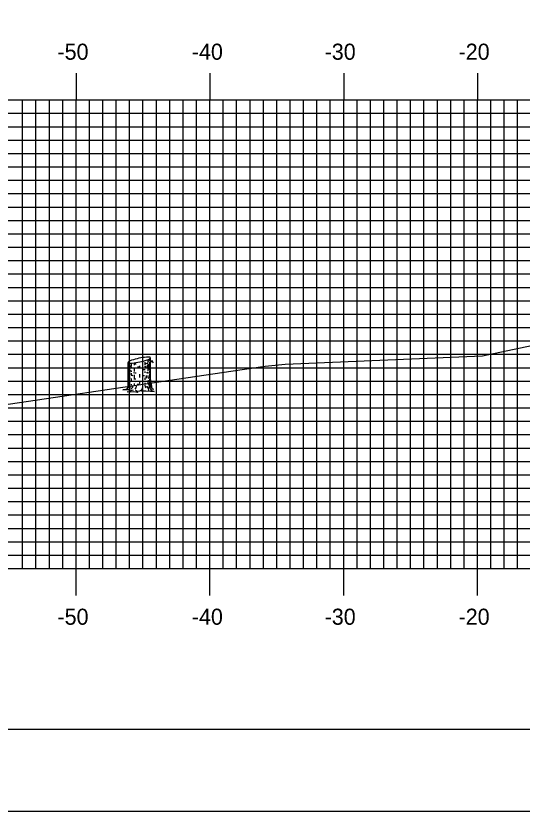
# Model space of a CAD drawing. Extents: x 852542 to 852886, y 364366 to 364586.
# Drawn here: x 852653.7 to 852691.5, y 364365.7 to 364425.1 of the extents above; entities that cross this region are included whole.
import ezdxf

# ---------------------------------------------------------------- set-up
doc = ezdxf.new("R2010")
doc.units = 0
for name, color, linetype in [('BORDER', 7, 'Continuous'), ('H_V ANNOTATION', 7, 'Continuous'), ('M_Trees_Conifer_Pay', 7, 'Continuous'), ('MAJOR', 7, 'Continuous'), ('MINOR', 7, 'Continuous'), ('PLOT BOUNDARY', 7, 'Continuous'), ('S_Roadway_Centerline', 7, 'Continuous')]:
    doc.layers.add(name, color=color, linetype=linetype)

msp = doc.modelspace()

# ---------------------------------------------------------------- linework, layer by layer
at = {"layer": 'BORDER'}
msp.add_lwpolyline([(852558.578, 364371.787), (852878.578, 364371.787), (852878.578, 364581.787), (852558.578, 364581.787)], close=True, dxfattribs=at)
at = {"layer": 'M_Trees_Conifer_Pay'}
for p, q in [((852663.548, 364399.388), (852663.548, 364399.165)), ((852663.666, 364399.449), (852663.666, 364399.287)), ((852663.737, 364397.875), (852663.737, 364399.522)), ((852662.073, 364397.465), (852662.073, 364399.186)), ((852662.12, 364399.149), (852662.12, 364398.678)), ((852662.179, 364399.138), (852662.179, 364399.04)), ((852662.179, 364398.966), (852662.179, 364398.762)), ((852662.304, 364399.13), (852662.304, 364398.898)), ((852662.304, 364398.857), (852662.304, 364398.783)), ((852662.524, 364399.15), (852662.524, 364398.982)), ((852662.524, 364398.745), (852662.524, 364398.509)), ((852662.929, 364398.919), (852662.929, 364398.824)), ((852663.32, 364399.192), (852663.32, 364398.993)), ((852663.32, 364398.935), (852663.32, 364398.846)), ((852663.548, 364399.077), (852663.548, 364399.03)), ((852663.605, 364398.894), (852663.554, 364398.834)), ((852663.666, 364399.219), (852663.666, 364399.091)), ((852663.666, 364398.904), (852663.666, 364398.568)), ((852662.12, 364398.614), (852662.12, 364398.305)), ((852662.12, 364398.258), (852662.12, 364397.766)), ((852662.179, 364398.704), (852662.179, 364398.505)), ((852662.179, 364398.457), (852662.179, 364398.121)), ((852662.304, 364398.379), (852662.304, 364398.241)), ((852662.524, 364398.264), (852662.524, 364398.112)), ((852662.929, 364398.305), (852662.929, 364398.231)), ((852662.929, 364398.206), (852662.929, 364398.058)), ((852663.32, 364398.499), (852663.32, 364398.394)), ((852663.548, 364398.694), (852663.548, 364398.562)), ((852663.548, 364398.451), (852663.548, 364398.342)), ((852663.548, 364398.206), (852663.548, 364398.064)), ((852663.666, 364398.532), (852663.666, 364398.369)), ((852663.666, 364398.322), (852663.666, 364398.105)), ((852662.12, 364397.712), (852662.12, 364397.465)), ((852662.179, 364398.068), (852662.179, 364397.932)), ((852662.179, 364397.833), (852662.179, 364397.455)), ((852662.304, 364397.969), (852662.304, 364397.827)), ((852662.304, 364397.566), (852662.304, 364397.471)), ((852662.524, 364398.068), (852662.524, 364397.895)), ((852662.524, 364397.617), (852662.524, 364397.465)), ((852662.929, 364397.766), (852662.929, 364397.613)), ((852663.32, 364398.027), (852663.32, 364397.881)), ((852663.32, 364397.648), (852663.32, 364397.56)), ((852663.548, 364397.837), (852663.548, 364397.665)), ((852663.666, 364398.074), (852663.666, 364398)), ((852663.666, 364397.959), (852663.666, 364397.786)), ((852662.304, 364397.072), (852662.467, 364397.135)), ((852662.741, 364397.007), (852662.615, 364397.072))]:
    msp.add_line(p, q, dxfattribs=at)
for points in [[(852663.521, 364398.982), (852663.49, 364398.898), (852663.486, 364398.83), (852663.517, 364398.766)], [(852663.554, 364399.02), (852663.591, 364398.946), (852663.638, 364399.003), (852663.696, 364399.071), (852663.788, 364399.264), (852663.853, 364399.312), (852663.884, 364399.318)], [(852663.569, 364398.766), (852663.605, 364398.894), (852663.669, 364399.009), (852663.7, 364399.077), (852663.769, 364399.223)], [(852663.783, 364399.253), (852663.859, 364399.261), (852663.931, 364399.161)], [(852662.252, 364398.492), (852662.246, 364398.587), (852662.29, 364398.564), (852662.29, 364398.47)], [(852663.391, 364398.093), (852663.404, 364398.016), (852663.451, 364398.027), (852663.439, 364398.194)], [(852663.737, 364397.875), (852663.788, 364397.613), (852663.805, 364397.339), (852663.863, 364397.214), (852663.998, 364397.183), (852663.768, 364397.146), (852663.768, 364397.146), (852663.774, 364397.098), (852664.021, 364397.004), (852663.747, 364397.02), (852663.391, 364397.041), (852663.07, 364397.03), (852663.076, 364397.113), (852662.928, 364397.03), (852662.741, 364397.007), (852662.765, 364396.94), (852662.498, 364396.983), (852662.277, 364396.956), (852661.985, 364396.973), (852662.273, 364397.03), (852662.304, 364397.072), (852662.141, 364397.129), (852661.905, 364397.14), (852661.664, 364397.14), (852662.006, 364397.198), (852662.047, 364397.278), (852662.073, 364397.465)], [(852663.564, 364397.587), (852663.638, 364397.482), (852663.643, 364397.308), (852663.768, 364397.146)], [(852663.663, 364397.732), (852663.669, 364397.587), (852663.716, 364397.518), (852663.727, 364397.319)], [(852662.121, 364397.417), (852662.1, 364397.339), (852662.08, 364397.245)], [(852662.199, 364397.397), (852662.205, 364397.282), (852662.152, 364397.193), (852662.141, 364397.129)], [(852662.362, 364397.424), (852662.362, 364397.292), (852662.273, 364397.193)], [(852662.588, 364397.183), (852662.656, 364397.278), (852662.683, 364397.417)], [(852663.076, 364397.113), (852663.151, 364397.255), (852663.16, 364397.356)], [(852663.327, 364397.482), (852663.338, 364397.356), (852663.412, 364397.312)], [(852663.605, 364397.093), (852663.591, 364397.23), (852663.517, 364397.36)]]:
    msp.add_lwpolyline(points, dxfattribs=at)
for centre, radius, start, end in [((852662.572, 364398.58), 0.802, 108.05939, 124.2194), ((852663.929, 364394.419), 5.179, 101.7194, 108.05939), ((852663.929, 364394.419), 5.179, 95.37941, 101.7194), ((852661.882, 364404.289), 5.179, 281.7194, 288.05939), ((852663.519, 364398.777), 0.802, 79.2194, 95.37941), ((852663.238, 364400.128), 0.802, 288.05939, 304.2194), ((852663.622, 364399.318), 0.251, 71.05013, 79.2194), ((852663.548, 364399.672), 0.251, 304.2194, 312.38868), ((852663.605, 364399.49), 0.172, 300, 311.25059), ((852663.677, 364399.478), 0.0817, 56.7194, 71.05013), ((852663.662, 364399.547), 0.0817, 312.38868, 326.7194), ((852663.678, 364399.408), 0.0624, 311.25059, 330), ((852663.692, 364399.502), 0.0527, 46.92298, 56.7194), ((852663.707, 364399.518), 0.0314, 34.2194, 46.92298), ((852663.686, 364399.531), 0.0527, 326.7194, 336.51582), ((852663.694, 364399.398), 0.0441, 330, 343.94846), ((852663.711, 364399.52), 0.0264, 23.40735, 34.2194), ((852663.715, 364399.522), 0.0226, 11.7194, 23.40735), ((852663.706, 364399.523), 0.0314, 336.51582, 349.2194), ((852663.704, 364399.395), 0.0334, 343.94846, 354.21506), ((852663.715, 364399.522), 0.0226, 0.03145, 11.7194), ((852663.711, 364399.522), 0.0264, 349.2194, 0.03145), ((852662.105, 364399.008), 0.0334, 163.94846, 180), ((852662.105, 364399.008), 0.0334, 180, 196.05154), ((852662.1, 364399.186), 0.0264, 169.2194, 180.03145), ((852662.096, 364399.186), 0.0226, 180.03145, 191.7194), ((852662.116, 364399.011), 0.0441, 196.05154, 210), ((852662.105, 364399.185), 0.0314, 156.51582, 169.2194), ((852662.096, 364399.186), 0.0226, 191.7194, 203.40735), ((852662.099, 364399.188), 0.0264, 203.40735, 214.2194), ((852662.124, 364399.177), 0.0527, 146.7194, 156.51582), ((852662.131, 364399.02), 0.0624, 210, 228.74941), ((852662.104, 364399.19), 0.0314, 214.2194, 226.92298), ((852662.148, 364399.161), 0.0817, 132.38868, 146.7194), ((852662.118, 364399.206), 0.0527, 226.92298, 236.7194), ((852662.134, 364399.23), 0.0817, 236.7194, 251.05013), ((852662.204, 364399.103), 0.172, 228.74941, 240), ((852662.262, 364399.036), 0.251, 124.2194, 132.38868), ((852662.189, 364399.39), 0.251, 251.05013, 259.2194), ((852662.403, 364399.448), 0.571, 240, 240.33672), ((852662.404, 364399.237), 0.571, 240, 247.05866), ((852662.292, 364399.931), 0.802, 259.2194, 275.37941), ((852662.403, 364399.448), 0.571, 246.85973, 257.98457), ((852661.882, 364404.289), 5.179, 275.37941, 281.7194), ((852662.905, 364403.198), 4.124, 264.6955, 266.73309), ((852662.904, 364402.965), 4.124, 268.07512, 270), ((852662.904, 364402.965), 4.124, 270, 270.35814), ((852662.904, 364402.965), 4.124, 275.78493, 277.05584), ((852662.905, 364403.198), 4.124, 276.23804, 278.1032), ((852663.406, 364399.681), 0.571, 278.1032, 284.36665), ((852663.406, 364399.835), 0.571, 284.43166, 292.41325), ((852663.406, 364399.237), 0.571, 284.44928, 297.04285), ((852663.406, 364399.681), 0.571, 297.0237, 300), ((852663.605, 364399.336), 0.172, 300, 311.25059), ((852663.678, 364399.253), 0.0624, 311.25059, 330), ((852663.694, 364399.244), 0.0441, 330, 343.94846), ((852663.704, 364399.241), 0.0334, 343.94846, 354.21506), ((852663.704, 364398.797), 0.0334, 343.94846, 354.21506), ((852662.105, 364398.561), 0.0334, 163.94846, 180), ((852662.105, 364398.561), 0.0334, 180, 196.05154), ((852662.105, 364398.351), 0.0334, 163.94846, 180), ((852662.105, 364398.351), 0.0334, 180, 196.05154), ((852662.116, 364398.564), 0.0441, 196.05154, 210), ((852662.116, 364398.354), 0.0441, 196.05154, 210), ((852662.131, 364398.573), 0.0624, 210, 228.74941), ((852662.131, 364398.363), 0.0624, 210, 228.74941), ((852662.204, 364398.656), 0.172, 228.74941, 240), ((852662.204, 364398.446), 0.172, 228.74941, 240), ((852662.403, 364399.001), 0.571, 240, 240.33672), ((852662.403, 364398.791), 0.571, 240, 246.85973), ((852662.403, 364398.791), 0.571, 259.27072, 261.8968), ((852662.904, 364402.309), 4.124, 261.8968, 263.14738), ((852662.904, 364402.519), 4.124, 264.08098, 266.66759), ((852662.904, 364402.309), 4.124, 270, 270.35814), ((852662.904, 364402.309), 4.124, 273.14934, 275.45691), ((852662.905, 364402.754), 4.124, 273.70524, 275.95043), ((852662.904, 364402.519), 4.124, 277.61247, 278.1032), ((852663.405, 364399.001), 0.571, 278.1032, 286.92962), ((852663.405, 364399.001), 0.571, 297.18959, 300), ((852663.405, 364398.791), 0.571, 297.18959, 300), ((852663.604, 364398.656), 0.172, 300, 311.25059), ((852663.604, 364398.446), 0.172, 300, 311.25059), ((852663.676, 364398.573), 0.0624, 311.25059, 330), ((852663.676, 364398.363), 0.0624, 311.25059, 330), ((852663.692, 364398.564), 0.0441, 330, 343.94846), ((852663.692, 364398.354), 0.0441, 330, 343.94846), ((852663.703, 364398.561), 0.0334, 343.94846, 354.21506), ((852663.703, 364398.351), 0.0334, 343.94846, 354.21506), ((852662.105, 364398.115), 0.0334, 163.94846, 180), ((852662.105, 364398.115), 0.0334, 180, 196.05154), ((852662.105, 364397.917), 0.0334, 163.94846, 180), ((852662.105, 364397.721), 0.0334, 163.94846, 180), ((852662.105, 364397.721), 0.0334, 180, 196.05154), ((852662.116, 364398.117), 0.0441, 196.05154, 210), ((852662.116, 364397.724), 0.0441, 196.05154, 210), ((852662.131, 364398.127), 0.0624, 210, 228.74941), ((852662.131, 364397.733), 0.0624, 210, 228.74941), ((852662.204, 364398.209), 0.172, 228.74941, 240), ((852662.204, 364397.816), 0.172, 228.74941, 240), ((852662.403, 364398.554), 0.571, 240, 246.85973), ((852662.392, 364398.363), 0.571, 241.23686, 248.02677), ((852662.403, 364398.161), 0.571, 240, 246.85973), ((852662.904, 364401.874), 4.124, 263.49906, 265.83975), ((852662.904, 364402.072), 4.124, 264.71603, 266.31934), ((852662.904, 364401.679), 4.124, 267.81166, 270), ((852662.904, 364401.679), 4.124, 270, 270.13279), ((852662.904, 364401.679), 4.124, 275.78493, 276.78961), ((852663.405, 364398.554), 0.571, 285.39827, 297.18959), ((852663.405, 364398.161), 0.571, 288.50673, 297.27208), ((852663.405, 364398.357), 0.571, 289.29072, 300), ((852663.604, 364398.012), 0.172, 300, 311.25059), ((852663.676, 364397.929), 0.0624, 311.25059, 330), ((852663.692, 364397.92), 0.0441, 330, 343.94846), ((852663.703, 364397.917), 0.0334, 343.94846, 354.21506), ((852662.105, 364397.501), 0.0334, 163.94846, 180), ((852662.105, 364397.501), 0.0334, 180, 196.05154), ((852662.116, 364397.504), 0.0441, 196.05154, 210), ((852662.131, 364397.513), 0.0624, 210, 228.74941), ((852662.204, 364397.596), 0.172, 228.74941, 240), ((852662.403, 364397.941), 0.571, 240, 244.53138), ((852662.904, 364401.458), 4.124, 262.44379, 263.51202), ((852662.904, 364401.458), 4.124, 277.36842, 278.1032), ((852663.405, 364397.941), 0.571, 278.1032, 281.63703), ((852663.604, 364397.596), 0.172, 300, 311.25059), ((852663.676, 364397.513), 0.0624, 311.25059, 330), ((852663.692, 364397.504), 0.0441, 330, 343.94846), ((852663.703, 364397.501), 0.0334, 343.94846, 354.21506)]:
    msp.add_arc(centre, radius, start, end, dxfattribs=at)
at = {"layer": 'MAJOR'}
for p, q in [((852658.178, 364420.791), (852658.178, 364418.787)), ((852668.178, 364420.791), (852668.178, 364418.787)), ((852678.178, 364420.791), (852678.178, 364418.787)), ((852688.178, 364420.791), (852688.178, 364418.787)), ((852568.178, 364418.787), (852848.178, 364418.787)), ((852568.178, 364418.787), (852848.178, 364418.787)), ((852658.178, 364383.787), (852658.178, 364418.787)), ((852668.178, 364383.787), (852668.178, 364418.787)), ((852678.178, 364383.787), (852678.178, 364418.787)), ((852688.178, 364383.787), (852688.178, 364418.787)), ((852568.178, 364413.787), (852848.178, 364413.787)), ((852568.178, 364408.787), (852848.178, 364408.787)), ((852568.178, 364403.787), (852848.178, 364403.787)), ((852568.178, 364398.787), (852848.178, 364398.787)), ((852568.178, 364393.787), (852848.178, 364393.787)), ((852568.178, 364388.787), (852848.178, 364388.787)), ((852568.178, 364383.787), (852848.178, 364383.787)), ((852568.178, 364383.787), (852848.178, 364383.787)), ((852658.178, 364381.783), (852658.178, 364383.787)), ((852668.178, 364381.783), (852668.178, 364383.787)), ((852678.178, 364381.783), (852678.178, 364383.787)), ((852688.178, 364381.783), (852688.178, 364383.787))]:
    msp.add_line(p, q, dxfattribs=at)
at = {"layer": 'MINOR'}
for p, q in [((852654.178, 364383.787), (852654.178, 364418.787)), ((852655.178, 364383.787), (852655.178, 364418.787)), ((852656.178, 364383.787), (852656.178, 364418.787)), ((852657.178, 364383.787), (852657.178, 364418.787)), ((852659.178, 364383.787), (852659.178, 364418.787)), ((852660.178, 364383.787), (852660.178, 364418.787)), ((852661.178, 364383.787), (852661.178, 364418.787)), ((852662.178, 364383.787), (852662.178, 364418.787)), ((852663.178, 364383.787), (852663.178, 364418.787)), ((852664.178, 364383.787), (852664.178, 364418.787)), ((852665.178, 364383.787), (852665.178, 364418.787)), ((852666.178, 364383.787), (852666.178, 364418.787)), ((852667.178, 364383.787), (852667.178, 364418.787)), ((852669.178, 364383.787), (852669.178, 364418.787)), ((852670.178, 364383.787), (852670.178, 364418.787)), ((852671.178, 364383.787), (852671.178, 364418.787)), ((852672.178, 364383.787), (852672.178, 364418.787)), ((852673.178, 364383.787), (852673.178, 364418.787)), ((852674.178, 364383.787), (852674.178, 364418.787)), ((852675.178, 364383.787), (852675.178, 364418.787)), ((852676.178, 364383.787), (852676.178, 364418.787)), ((852677.178, 364383.787), (852677.178, 364418.787)), ((852679.178, 364383.787), (852679.178, 364418.787)), ((852680.178, 364383.787), (852680.178, 364418.787)), ((852681.178, 364383.787), (852681.178, 364418.787)), ((852682.178, 364383.787), (852682.178, 364418.787)), ((852683.178, 364383.787), (852683.178, 364418.787)), ((852684.178, 364383.787), (852684.178, 364418.787)), ((852685.178, 364383.787), (852685.178, 364418.787)), ((852686.178, 364383.787), (852686.178, 364418.787)), ((852687.178, 364383.787), (852687.178, 364418.787)), ((852689.178, 364383.787), (852689.178, 364418.787)), ((852690.178, 364383.787), (852690.178, 364418.787)), ((852691.178, 364383.787), (852691.178, 364418.787)), ((852568.178, 364417.787), (852848.178, 364417.787)), ((852568.178, 364416.787), (852848.178, 364416.787)), ((852568.178, 364415.787), (852848.178, 364415.787)), ((852568.178, 364414.787), (852848.178, 364414.787)), ((852568.178, 364412.787), (852848.178, 364412.787)), ((852568.178, 364411.787), (852848.178, 364411.787)), ((852568.178, 364410.787), (852848.178, 364410.787)), ((852568.178, 364409.787), (852848.178, 364409.787)), ((852568.178, 364407.787), (852848.178, 364407.787)), ((852568.178, 364406.787), (852848.178, 364406.787)), ((852568.178, 364405.787), (852848.178, 364405.787)), ((852568.178, 364404.787), (852848.178, 364404.787)), ((852568.178, 364402.787), (852848.178, 364402.787)), ((852568.178, 364401.787), (852848.178, 364401.787)), ((852568.178, 364400.787), (852848.178, 364400.787)), ((852568.178, 364399.787), (852848.178, 364399.787)), ((852568.178, 364397.787), (852848.178, 364397.787)), ((852568.178, 364396.787), (852848.178, 364396.787)), ((852568.178, 364395.787), (852848.178, 364395.787)), ((852568.178, 364394.787), (852848.178, 364394.787)), ((852568.178, 364392.787), (852848.178, 364392.787)), ((852568.178, 364391.787), (852848.178, 364391.787)), ((852568.178, 364390.787), (852848.178, 364390.787)), ((852568.178, 364389.787), (852848.178, 364389.787)), ((852568.178, 364387.787), (852848.178, 364387.787)), ((852568.178, 364386.787), (852848.178, 364386.787)), ((852568.178, 364385.787), (852848.178, 364385.787)), ((852568.178, 364384.787), (852848.178, 364384.787))]:
    msp.add_line(p, q, dxfattribs=at)
at = {"layer": 'PLOT BOUNDARY'}
msp.add_lwpolyline([(852542.392, 364365.669), (852882.392, 364365.669), (852882.392, 364585.669), (852542.392, 364585.669)], close=True, dxfattribs=at)
at = {"layer": 'S_Roadway_Centerline'}
msp.add_lwpolyline([(852568.178, 364389.653), (852574.124, 364389.68), (852579.335, 364389.626), (852588.614, 364389.629), (852597.954, 364389.902), (852600.269, 364390.493), (852604.34, 364390.409), (852612.17, 364390.986), (852617.284, 364391.045), (852625.147, 364392.472), (852635.572, 364393.111), (852637.65, 364393.473), (852647.868, 364395.294), (852669.738, 364398.532), (852672.306, 364398.911), (852673.814, 364399.054), (852688.559, 364399.681), (852700.745, 364402.23)], dxfattribs=at)

# ---------------------------------------------------------------- texts
at = {"layer": 'H_V ANNOTATION'}
for s, p in [('-50', (852656.787, 364421.787)), ('-40', (852666.83, 364421.787)), ('-30', (852676.755, 364421.787)), ('-20', (852686.765, 364421.787)), ('-50', (852656.787, 364379.587)), ('-40', (852666.83, 364379.587)), ('-30', (852676.755, 364379.587)), ('-20', (852686.765, 364379.587))]:
    msp.add_text(s, height=1.2, dxfattribs=at).set_placement(p)

doc.saveas('drawing.dxf')
